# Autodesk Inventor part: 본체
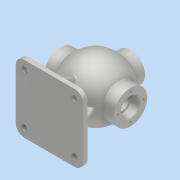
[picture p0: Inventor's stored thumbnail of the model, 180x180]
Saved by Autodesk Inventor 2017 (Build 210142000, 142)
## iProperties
Part Number: 본체
Material: 알루미늄 6061
Document SubType Name: Modeling
Designer: MRC
Density: 2.7 g/cm^3
Appearance: 알루미늄 - 평지
Mass: 1457.53 g
Surface Area: 1170.28 cm^2
Volume: 539.828 cm^3
Author: MRC
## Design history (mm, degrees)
sketch "스케치1"
  geometry: L1 (0, 54)-(0, -54); A1 r 54 centre (0, 0) between (0, -54) and (0, 54); 2 further points
  constraints: 2 coincident, 2 end point, 2 point on circle, 1 centre point, 1 midpoint, 1 vertical
  dimensions: "d2" = 108 diameter of A1
revolve "회전1" sketch "스케치1" stored, may be unused: angle "d3" = 90 deg
sketch "스케치2"
  geometry: L1 (0, 44)-(0, -44); A1 r 44 centre (0, 0) between (0, -44) and (0, 44); 2 further points
  constraints: 2 coincident, 2 end point, 2 point on circle, 1 centre point, 1 midpoint, 1 vertical
  dimensions: "d4" = 88 distance of L1.start L1.end
revolve "회전2" sketch "스케치2" stored, may be unused: angle "d5" = 90 deg
node "작업 평면1"
sketch "스케치3"
  geometry: C1 r 31 at (0, 0); 1 further point
  constraints: 1 centre point, 1 coincident
  dimensions: "d7" = 62 diameter of C1
extrude "돌출1" join sketch "스케치3" stored distance "d8" = 16; taper "d9" = 0 deg
sketch "스케치4"
  geometry: C1 r 17.5 at (0, 0); 1 further point
  constraints: 1 centre point, 1 coincident
  dimensions: "d10" = 35 diameter of C1
extrude "돌출2" cut sketch "스케치4" distance "d11" = 16; taper "d12" = 0 deg
sketch "스케치5"
  geometry: C1 r 15 at (0, 0); 1 further point
  constraints: 1 centre point, 1 coincident
  dimensions: "d13" = 30 diameter of C1
extrude "돌출3" cut sketch "스케치5" stored distance "d14" = 16; taper "d15" = 0 deg
fillet "모깎기1" dims "d16" = 0.6
chamfer "모따기1" distance "d17" = 1; stored, may be unused: second distance "d18" = 2, angle "d19" = 45 deg
sketch "스케치7"
  geometry: L1 (-62.5, -75)-(62.5, -75); L2 (62.5, -75)-(62.5, -85); L3 (62.5, -85)-(-62.5, -85); L4 (-62.5, -85)-(-62.5, -75); 2 further points
  constraints: 8 end point, 2 parallel, 1 horizontal, 1 midpoint, 1 perpendicular, 1 vertical alignment
  dimensions: "d20" = 125 distance of L1.start L1.end; "d21" = 10 distance of L1.end L2.end; "d22" = 85 distance from line of L3 point (0, 0)
extrude "돌출4" join sketch "스케치7" stored distance "d23" = 125; taper "d24" = 0 deg
sketch "스케치8"
  geometry: L1 (50.5, -75)-(39.971, -46.072); L2 (-50.5, -75)-(-41.337, -49.825); L3 (-62.5, -75)-(62.5, -75) reference; L4 (62.5, -75)-(62.5, -85) reference; L5 (-62.5, -85)-(-62.5, -75) reference; 1 further point
  constraints: 4 end point, 2 point on line
  dimensions: "d25" = 12 distance from line of L4 L1.start; "d26" = 12 distance of L3.start L2.start; "d28" = 20 deg angle of L1 L4; "d29" = 20 deg angle of L2 L5
feature "리브1" dims "d30" = 40, "d31" = 8, "d32" = 0, "d33" = 0, "d34" = 1, "d35" = 1
feature "리브2" dims "d36" = 40, "d37" = 8, "d38" = 0, "d39" = 0, "d40" = 1, "d41" = 1
sketch "스케치9"
  geometry: L1 (-75, 50.5)-(-46.657, 40.184); L2 (-75, -50.5)-(-48.7, -40.928); L3 (-75, -62.5)-(-85, -62.5) reference; L4 (-85, 62.5)-(-75, 62.5) reference; L5 (-85, 62.5)-(-85, -62.5) reference; L6 (-75, -62.5)-(-85, -62.5) reference; L7 (-75, 62.5)-(-75, -62.5) reference; L8 (-85, 62.5)-(-75, 62.5) reference; 1 further point
  constraints: 4 end point, 2 point on line
  dimensions: "d42" = 20 deg angle of L1 L4; "d43" = 20 deg angle of L2 L3; "d44" = 12 distance of L3.start L2.start; "d45" = 12 distance of L4.end L1.start
  node "투영된 루프1"
feature "리브3" dims "d46" = 40, "d47" = 8, "d48" = 0, "d49" = 0, "d50" = 1, "d51" = 1
feature "리브4" dims "d52" = 40, "d53" = 8, "d54" = 0, "d55" = 0, "d56" = 1, "d57" = 1
fillet "모깎기2" dims "d58" = 3
fillet "모깎기3" dims "d59" = 3
fillet "모깎기4" dims "d60" = 3
fillet "모깎기5" dims "d61" = 16
node "작업 평면2"
sketch "스케치10"
  geometry: C1 r 27 at (0, 0); 1 further point
  constraints: 1 centre point, 1 coincident
  dimensions: "d63" = 54 diameter of C1
extrude "돌출5" join sketch "스케치10" stored distance "d64" = 125; taper "d65" = 0 deg
sketch "스케치11"
  geometry: C1 r 13 at (0, 0); 1 further point
  constraints: 1 centre point, 1 coincident
  dimensions: "d66" = 26 diameter of C1
extrude "돌출6" cut sketch "스케치11" stored distance "d67" = 125; taper "d68" = 0 deg
fillet "모깎기6" dims "d69" = 3
sketch "스케치12"
  geometry: 2 further points
  constraints: 1 vertical alignment
  dimensions: "d70" = 24 distance of point (0, 0) point (0, 24)
hole "구멍1" sketch "스케치12" at (0, 24) diameter "d71" = 3.242; stored, may be unused: countersink angle "d75" = 90 deg, drill point angle "d77" = 118 deg; dims "d72" = 12, "d73" = 4, "d74" = 2, "d76" = 15
sketch "스케치13"
  geometry: 2 further points
  constraints: 1 vertical alignment
  dimensions: "d81" = 20 distance of point (0, 20) point (0, 0)
hole "구멍2" sketch "스케치13" at (0, 20) diameter "d82" = 3.242; stored, may be unused: countersink angle "d86" = 90 deg, drill point angle "d88" = 118 deg; dims "d83" = 9, "d84" = 4, "d85" = 2, "d87" = 11
sketch "스케치14"
  geometry: L1 (-16, 16)-(-16, 109) reference; L2 (93, 125)-(0, 125) reference; L3 (109, 16)-(109, 109) reference; L4 (0, 0)-(93, 0) reference; C1 r 5.5 at (0, 109); C2 r 5.5 at (0, 16); C3 r 5.5 at (93, 109); C4 r 5.5 at (93, 16); A1 r 16 centre (0, 16) between (-16, 16) and (0, 0) reference; A2 r 16 centre (0, 109) between (0, 125) and (-16, 109) reference; A3 r 16 centre (93, 109) between (109, 109) and (93, 125) reference; A4 r 16 centre (93, 16) between (93, 0) and (109, 16) reference; 1 further point
  constraints: 4 centre point, 4 coincident
  dimensions: "d92" = 11 diameter of C1; "d93" = 11 diameter of C2; "d94" = 11 diameter of C3; "d95" = 11 diameter of C4
extrude "돌출7" cut sketch "스케치14" distance "d96" = 125; taper "d97" = 0 deg
fillet "모깎기7" dims "d98" = 3
fillet "모깎기8" dims "d99" = 3
node "작업 평면3"
sketch "스케치15"
  geometry: L1 (1.621, 54)-(1.621, 65) reference; L2 (-27, 65)-(27, 65) reference; L3 (-27, 48.466)-(27, 48.466) reference; L4 (-43.341, 32.211)-(-43.341, -32.211) reference; L5 (-6.632, -41.403)-(-6.632, -53.179) reference; L6 (6.632, -53.179)-(6.632, -41.403) reference; L7 (38.706, -37.642)-(38.706, -37.642) reference; L8 (6.632, -41.403)-(6.632, -53.179) reference; L9 (-6.632, -53.179)-(-6.632, -41.403) reference; L10 (-38.706, -37.642)-(-38.706, -37.642) reference; L11 (43.341, -32.211)-(43.341, 32.211) reference; L12 (28.421, 45.916)-(-28.421, 45.916) reference; A1 r 53.591 centre (0, 0) between (-34.026, -41.403) and (-6.632, -53.179) reference; A2 r 53.591 centre (0, 0) between (6.632, -53.179) and (34.026, -41.403) reference; A3 r 53.591 centre (0, 0) between (6.632, -53.179) and (34.026, -41.403) reference; A4 r 53.591 centre (0, 0) between (-34.026, -41.403) and (-6.632, -53.179) reference; 8 further points; 2 other entities
  constraints: 1 vertical alignment, 11 other
  dimensions: "d101" = 9 distance from line of L2 point (0, 56)
feature "엠보싱1" sketch "스케치15" dims "d10" = 35, "d102" = 0.5, "d103" = 0
chamfer "모따기2" distance "d104" = 1; stored, may be unused: second distance "d105" = 2, angle "d106" = 45 deg
node "솔리드1"
mirror "미러1"
pattern_circular "원형 패턴1" dims angle "d79" = 360 deg
mirror "미러2"
pattern_circular "원형 패턴2" dims angle "d90" = 360 deg
node "투영된 루프2"
node "투영된 루프3"
node "투영된 루프4"
other parameters: "d6" = 65, "d62" = 65, "d100" = -27
